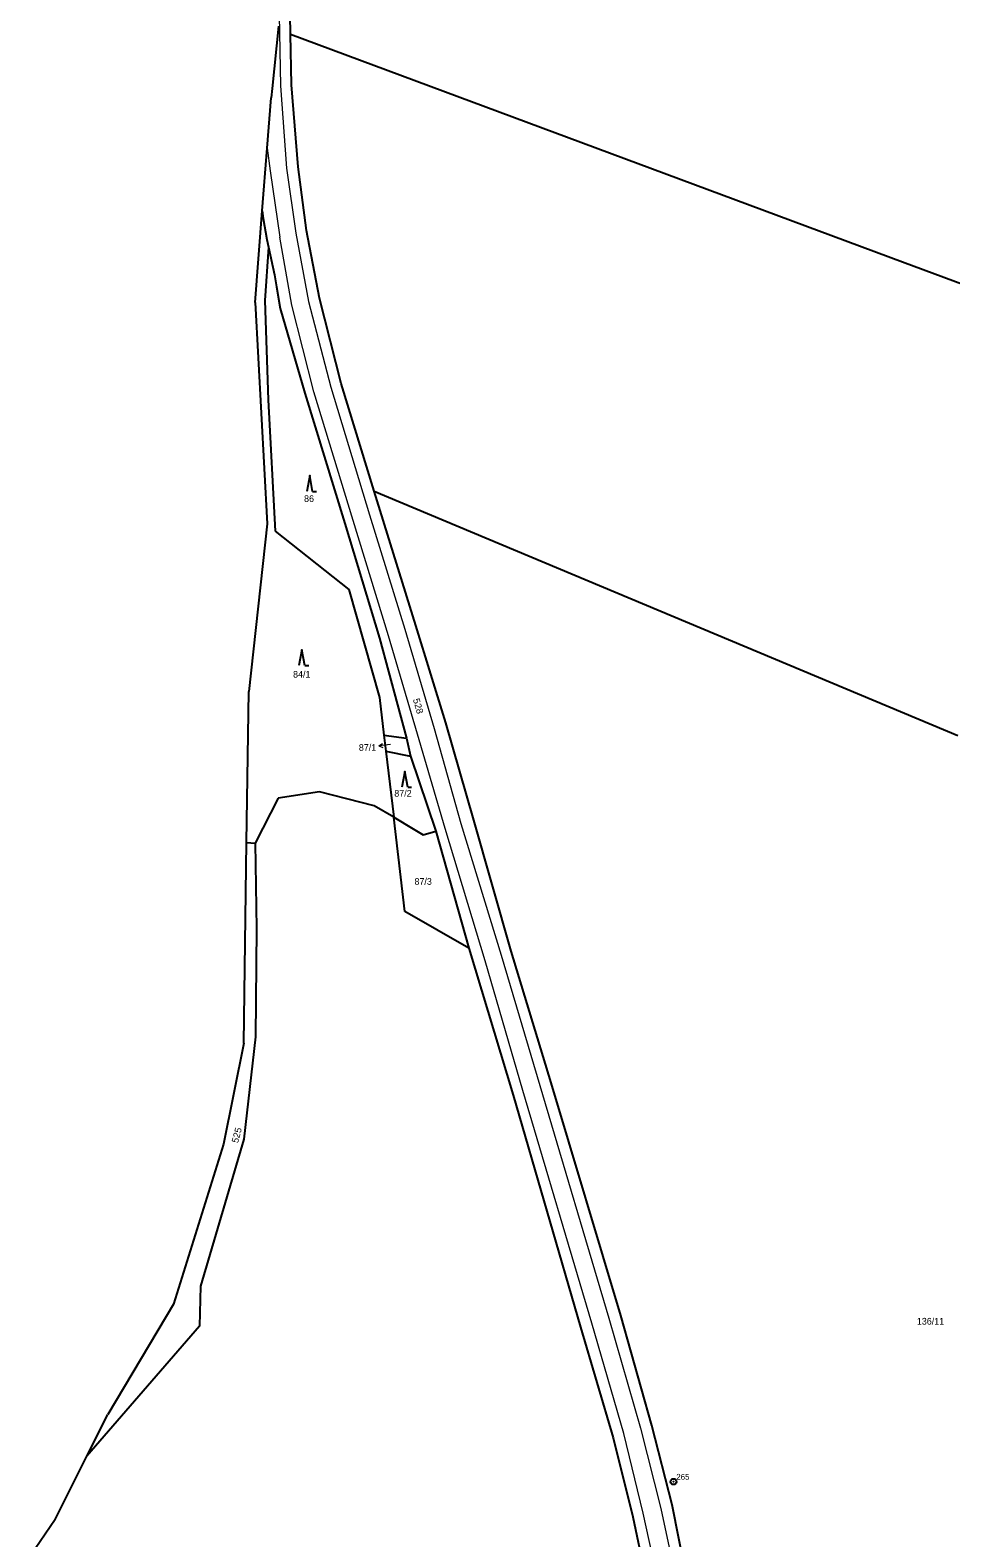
# Model space of a CAD drawing. Extents: x -885985 to -883535, y -1030025 to -1027941.
# Drawn here: x -885831.6 to -885597.1, y -1028684.8 to -1028300.8 of the extents above; entities that cross this region are included whole.
import ezdxf
from ezdxf.enums import TextEntityAlignment as Align

# ---------------------------------------------------------------- set-up
doc = ezdxf.new("R2010")
doc.units = 0
doc.header["$LTSCALE"] = 0.68
for name, color, linetype, lineweight in [('1', 7, 'Continuous', 25), ('3', 7, 'Continuous', 25), ('4', 7, 'Continuous', 13), ('7', 7, 'Continuous', 13), ('8', 7, 'Continuous', 25)]:
    doc.layers.add(name, color=color, linetype=linetype, lineweight=lineweight)
doc.layers.add('2', color=7, linetype='Continuous')

msp = doc.modelspace()

# ---------------------------------------------------------------- linework, layer by layer
at = {"layer": '1'}
for p, q in [((-885765.26, -1028301.8), (-885765.44, -1028291.63)), ((-885768.32, -1028299.71), (-885769.93, -1028315.6)), ((-885765.26, -1028301.8), (-885609.36, -1028359.75)), ((-885765.04, -1028314.65), (-885765.26, -1028301.8)), ((-885769.93, -1028315.6), (-885770.17, -1028318.01)), ((-885763.32, -1028335.6), (-885765.04, -1028314.65)), ((-885771.19, -1028330.82), (-885770.17, -1028318.01)), ((-885772.45, -1028346.74), (-885771.19, -1028330.82)), ((-885761.17, -1028351.8), (-885763.32, -1028335.6)), ((-885774.3, -1028370.09), (-885772.45, -1028346.74)), ((-885772.45, -1028346.74), (-885772.23, -1028348.75)), ((-885772.23, -1028348.75), (-885771.28, -1028354.08)), ((-885757.89, -1028369.04), (-885761.17, -1028351.8)), ((-885771.28, -1028354.08), (-885770.86, -1028356.04)), ((-885770.86, -1028356.04), (-885771.79, -1028369.59)), ((-885770.86, -1028356.04), (-885769.34, -1028363.08)), ((-885769.34, -1028363.08), (-885768.85, -1028366.09)), ((-885609.36, -1028359.75), (-885453.46, -1028417.7)), ((-885768.85, -1028366.09), (-885767.93, -1028371.62)), ((-885774.3, -1028370.09), (-885771.19, -1028426.5)), ((-885771.79, -1028369.59), (-885770.93, -1028394.88)), ((-885752.38, -1028390.76), (-885757.89, -1028369.04)), ((-885767.93, -1028371.62), (-885761.6, -1028393.23)), ((-885761.6, -1028393.23), (-885751.46, -1028426.37)), ((-885743.95, -1028418.15), (-885752.38, -1028390.76)), ((-885770.93, -1028394.88), (-885769.19, -1028428.34)), ((-885733.36, -1028452.37), (-885743.95, -1028418.15)), ((-885743.95, -1028418.15), (-885595.26, -1028480.4)), ((-885771.19, -1028426.5), (-885775.92, -1028469.22)), ((-885769.19, -1028428.34), (-885750.44, -1028443.21)), ((-885751.46, -1028426.37), (-885742.59, -1028455.62)), ((-885750.44, -1028443.21), (-885742.61, -1028470.73)), ((-885742.59, -1028455.62), (-885735.77, -1028481.1)), ((-885725.73, -1028477.21), (-885733.36, -1028452.37)), ((-885776.45, -1028507.63), (-885775.92, -1028469.22)), ((-885742.61, -1028470.73), (-885741.47, -1028480.32)), ((-885718.59, -1028501.97), (-885725.73, -1028477.21)), ((-885741.47, -1028480.32), (-885735.77, -1028481.1)), ((-885741.47, -1028480.32), (-885740.99, -1028484.36)), ((-885735.77, -1028481.1), (-885734.74, -1028485.67)), ((-885740.99, -1028484.36), (-885738.98, -1028501.23)), ((-885740.99, -1028484.36), (-885734.74, -1028485.67)), ((-885734.74, -1028485.67), (-885728.28, -1028504.81)), ((-885768.43, -1028496.35), (-885774.28, -1028507.86)), ((-885757.89, -1028494.77), (-885768.43, -1028496.35)), ((-885743.95, -1028498.31), (-885757.89, -1028494.77)), ((-885738.98, -1028501.23), (-885743.95, -1028498.31)), ((-885736.12, -1028525.23), (-885738.98, -1028501.23)), ((-885738.98, -1028501.23), (-885734.02, -1028504.14)), ((-885734.02, -1028504.14), (-885731.51, -1028505.71)), ((-885731.51, -1028505.71), (-885728.28, -1028504.81)), ((-885728.28, -1028504.81), (-885719.87, -1028534.59)), ((-885709.03, -1028535.32), (-885718.59, -1028501.97)), ((-885777.16, -1028558.77), (-885776.45, -1028507.63)), ((-885776.45, -1028507.63), (-885774.28, -1028507.86)), ((-885774.28, -1028507.86), (-885773.94, -1028529.56)), ((-885719.87, -1028534.59), (-885736.12, -1028525.23)), ((-885773.94, -1028529.56), (-885774.22, -1028557.11)), ((-885719.87, -1028534.59), (-885708.6, -1028571.98)), ((-885698.86, -1028568.87), (-885709.03, -1028535.32)), ((-885777.16, -1028558.77), (-885782.32, -1028584.51)), ((-885774.22, -1028557.11), (-885777.17, -1028583.25)), ((-885681.13, -1028628.15), (-885698.86, -1028568.87)), ((-885708.6, -1028571.98), (-885691.4, -1028631.13)), ((-885782.32, -1028584.51), (-885795.11, -1028625.28)), ((-885777.17, -1028583.25), (-885788.24, -1028620.63)), ((-885788.24, -1028620.63), (-885788.45, -1028630.82)), ((-885795.11, -1028625.28), (-885811.84, -1028653.35)), ((-885673.2, -1028656.12), (-885681.13, -1028628.15)), ((-885788.45, -1028630.82), (-885817.17, -1028663.96)), ((-885691.4, -1028631.13), (-885683.12, -1028659.26)), ((-885817.17, -1028663.96), (-885811.84, -1028653.35)), ((-885668.08, -1028676.33), (-885673.2, -1028656.12)), ((-885683.12, -1028659.26), (-885678.06, -1028679.39)), ((-885825.26, -1028680.06), (-885817.17, -1028663.96)), ((-885662.04, -1028706.6), (-885668.08, -1028676.33)), ((-885825.26, -1028680.06), (-885831.59, -1028689.45)), ((-885678.06, -1028679.39), (-885672.35, -1028706.69))]:
    msp.add_line(p, q, dxfattribs=at)
at = {"layer": '3'}
for p, q in [((-885759.63, -1028418.22), (-885758.634, -1028418.22)), ((-885761.64, -1028462.58), (-885760.644, -1028462.58)), ((-885735.43, -1028493.56), (-885734.434, -1028493.56))]:
    msp.add_line(p, q, dxfattribs=at)
for points in [[(-885759.63, -1028418.22), (-885760.38, -1028414.22), (-885761.13, -1028418.22)], [(-885761.64, -1028462.58), (-885762.39, -1028458.58), (-885763.14, -1028462.58)], [(-885735.43, -1028493.56), (-885736.18, -1028489.56), (-885736.93, -1028493.56)]]:
    msp.add_lwpolyline(points, dxfattribs=at)
at = {"layer": '4'}
for p, q in [((-885768.24, -1028291.78), (-885767.81, -1028314.94)), ((-885767.81, -1028314.94), (-885766.3, -1028335.94)), ((-885771.19, -1028330.82), (-885770.42, -1028336.57)), ((-885770.42, -1028336.57), (-885768.03, -1028353.51)), ((-885766.3, -1028335.94), (-885763.94, -1028352.44)), ((-885764.97, -1028370.79), (-885768.03, -1028353.51)), ((-885763.94, -1028352.44), (-885760.68, -1028369.85)), ((-885759.34, -1028392.9), (-885764.97, -1028370.79)), ((-885760.68, -1028369.85), (-885754.99, -1028391.66)), ((-885749.34, -1028425.62), (-885759.34, -1028392.9)), ((-885754.99, -1028391.66), (-885745.19, -1028424.23)), ((-885745.19, -1028424.23), (-885736.18, -1028453.3)), ((-885740.31, -1028455.01), (-885749.34, -1028425.62)), ((-885732.93, -1028480.08), (-885740.31, -1028455.01)), ((-885736.18, -1028453.3), (-885728.69, -1028478.65)), ((-885728.69, -1028478.65), (-885721.89, -1028502.81)), ((-885725.91, -1028504.12), (-885732.93, -1028480.08)), ((-885715.68, -1028537.79), (-885725.91, -1028504.12)), ((-885721.89, -1028502.81), (-885711.64, -1028536.38)), ((-885706.12, -1028570.86), (-885715.68, -1028537.79)), ((-885711.64, -1028536.38), (-885701.73, -1028569.55)), ((-885688.54, -1028630.08), (-885706.12, -1028570.86)), ((-885701.73, -1028569.55), (-885684.22, -1028628.8)), ((-885680.4, -1028658.14), (-885688.54, -1028630.08)), ((-885684.22, -1028628.8), (-885676.12, -1028656.82)), ((-885675.45, -1028678.46), (-885680.4, -1028658.14)), ((-885676.12, -1028656.82), (-885670.93, -1028677.24)), ((-885670.93, -1028677.24), (-885665.08, -1028705.02)), ((-885669.32, -1028706.07), (-885675.45, -1028678.46))]:
    msp.add_line(p, q, dxfattribs=at)
at = {"layer": '7'}
msp.add_line((-885742.779, -1028483.046), (-885741.724, -1028483.421), dxfattribs=at)
msp.add_lwpolyline([(-885739.8, -1028482.68), (-885742.779, -1028483.046), (-885741.846, -1028482.427)], dxfattribs=at)
at = {"layer": '8'}
for radius in [0.75, 0.03]:
    msp.add_circle((-885667.73, -1028670.4498), radius, dxfattribs=at)

# ---------------------------------------------------------------- texts
at = {"layer": '2'}
for s, p in [('86', (-885761.82, -1028420.915)), ('84/1', (-885764.62, -1028465.665)), ('87/2', (-885738.84, -1028495.985)), ('87/3', (-885733.7, -1028518.425)), ('136/11', (-885605.73, -1028630.435))]:
    msp.add_text(s, height=1.7, dxfattribs=at).set_placement(p)
at = {"layer": '2', "width": 1.05}
for s, rotation, p in [('528', 286, (-885734.108, -1028471.217)), ('525', 75, (-885778.669, -1028584.339))]:
    msp.add_text(s, height=1.7, rotation=rotation, dxfattribs=at).set_placement(p)
at = {"layer": '2'}
msp.add_text('87/1', height=1.7, dxfattribs=at).set_placement((-885745.659, -1028484.305), align=Align.CENTER)
at = {"layer": '8'}
msp.add_text('265', height=1.5, dxfattribs=at).set_placement((-885663.657, -1028669.966), align=Align.RIGHT)

doc.saveas('drawing.dxf')
